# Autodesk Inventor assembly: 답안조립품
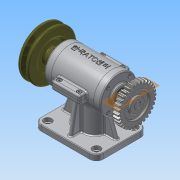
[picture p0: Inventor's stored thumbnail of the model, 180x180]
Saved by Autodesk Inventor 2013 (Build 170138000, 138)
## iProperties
Created: 2015-09
Part Number: 답안조립품
Document SubType Name: Assembly
Designer: Administrator
Mass: 2251.17 g
Surface Area: 1633.51 cm^2
Volume: 528.515 cm^3
Density: 4.25943 g/cm^3
Author: Administrator
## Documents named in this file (17)
- C:\Users\Administrator\Desktop\350908V1023\답안조립품.iam
- C:\Users\Administrator\Desktop\350908V1023\본체.ipt
- C:\Users\Administrator\Desktop\350908V1023\M3x0.5x8.ipt
- C:\Users\Administrator\Desktop\350908V1023\M4x0.5x14.ipt
- C:\Users\Administrator\Desktop\350908V1023\V-벨트풀리.ipt
- C:\Users\Administrator\Desktop\350908V1023\뒤커버.ipt
- C:\Users\Administrator\Desktop\350908V1023\멈춤나사.ipt
- C:\Users\Administrator\Desktop\350908V1023\베어링 6201.ipt
- C:\Users\Administrator\Desktop\350908V1023\베어링 6202.ipt
- C:\Users\Administrator\Desktop\350908V1023\본체 커버.ipt
- C:\Users\Administrator\Desktop\350908V1023\스퍼기어.ipt
- C:\Users\Administrator\Desktop\350908V1023\슬라이드.ipt
- C:\Users\Administrator\Desktop\350908V1023\앞커버.ipt
- C:\Users\Administrator\Desktop\350908V1023\오일실.ipt
- C:\Users\Administrator\Desktop\350908V1023\키4x4.ipt
- C:\Users\Administrator\Desktop\350908V1023\편심축.ipt
- C:\Users\Administrator\Desktop\350908V1023\가변스프링.ipt
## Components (14 placed, 4 different names)
1. V-벨트풀리:1 — 플러쉬:2, 각도:1
2. 가변스프링:1
3. M4x0.5x14:1
4. M4x0.5x14:2
5. M4x0.5x14:3
6. M4x0.5x14:4
7. M3x0.5x8:1
8. M3x0.5x8:2
9. M3x0.5x8:3
10. M3x0.5x8:4
11. M3x0.5x8:5
12. M3x0.5x8:6
13. M3x0.5x8:7
14. M3x0.5x8:8
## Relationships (2: Flush 1, Angle 1)
- 플러쉬:2 [Flush]: V-벨트풀리:1
- 각도:1 [Angle]: V-벨트풀리:1
